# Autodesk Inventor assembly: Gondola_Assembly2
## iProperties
Shininess: 64.0
Length Units: 11272
Angle Units: 11279
Time Units: 11290
Mass Units: 11286
Length Display Precision: 3
Angle Display Precision: 2
Compacted: True
Part Number: Gondola_Assembly2
Document SubType Name: Assembly
Created: 2004-08
Designer: John Blackburn
Manufacturer: Standard
Standards Organization: Custom
Density: 0.0
Volumn: 0.0
Area: 0.0
PropertySet Name: Model Information
Control State: 0
Master: False
Checked Out: False
Author: John Blackburn
